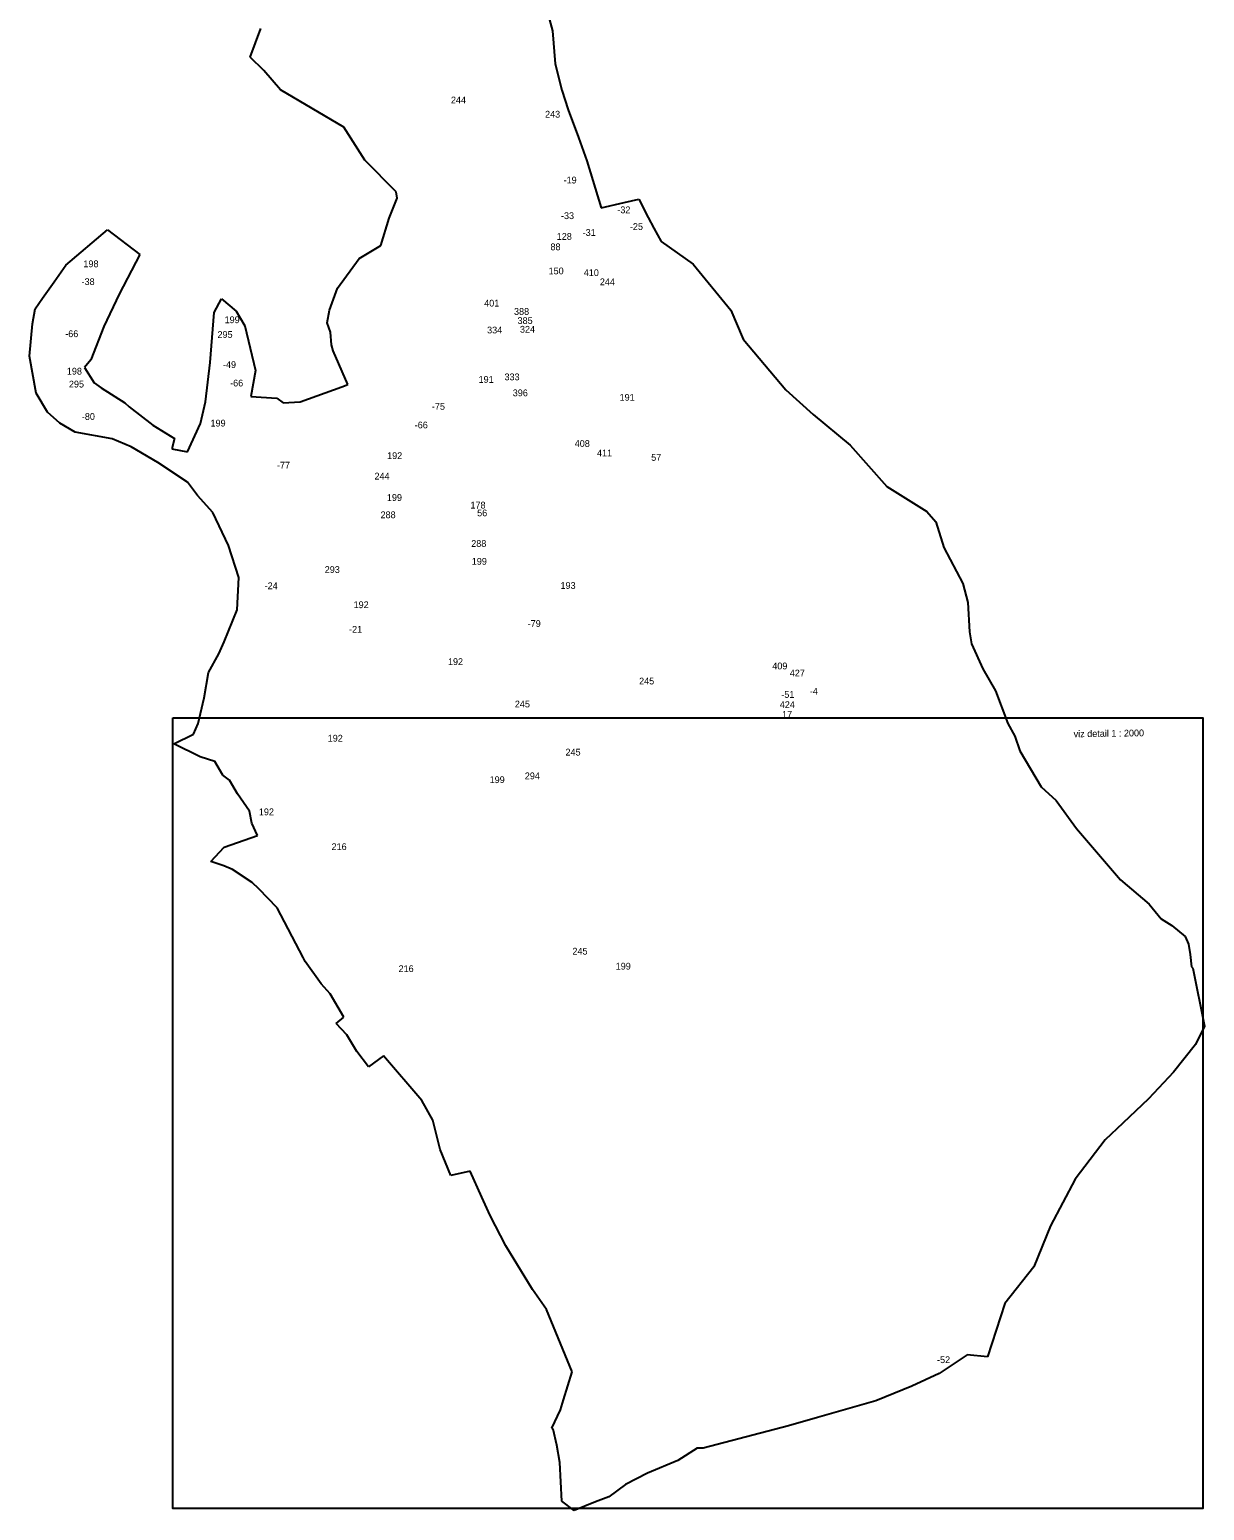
# Model space of a CAD drawing. Extents: x -783664 to -781808, y -970520 to -966149.
# Drawn here: x -783545 to -781808, y -970520 to -968331 of the extents above; entities that cross this region are included whole.
import ezdxf

# ---------------------------------------------------------------- set-up
doc = ezdxf.new("R2010")
doc.units = 0
for name, color, linetype in [('Vrstva 1', 7, 'Continuous'), ('Vrstva 13', 7, 'Continuous'), ('Vrstva 15', 7, 'Continuous'), ('Vrstva 24', 7, 'Continuous')]:
    doc.layers.add(name, color=color, linetype=linetype)

msp = doc.modelspace()

# ---------------------------------------------------------------- linework, layer by layer
at = {"layer": 'Vrstva 1'}
msp.add_lwpolyline([(-783332.78, -969348.53), (-781809.77, -969348.53), (-781809.77, -970517.05), (-783332.78, -970517.05)], close=True, dxfattribs=at)
at = {"layer": 'Vrstva 13'}
for p, q in [((-782785.02, -968283.61), (-782771.42, -968332.9)), ((-783218.65, -968371.67), (-783202.86, -968329.23)), ((-782771.42, -968332.9), (-782767.35, -968381.74)), ((-783198.33, -968391.67), (-783218.65, -968371.67)), ((-782767.35, -968381.74), (-782757.92, -968420.6)), ((-783173.85, -968419.84), (-783198.33, -968391.67)), ((-783079.89, -968475.16), (-783173.85, -968419.84)), ((-782757.92, -968420.6), (-782748.39, -968449.45)), ((-782748.39, -968449.45), (-782732.98, -968490.32)), ((-783048.86, -968523.96), (-783079.89, -968475.16)), ((-782732.98, -968490.32), (-782720.6, -968524.88)), ((-783002.81, -968571), (-783048.86, -968523.96)), ((-782720.6, -968524.88), (-782699.6, -968594.28)), ((-783013.22, -968609.55), (-783001.16, -968580.41)), ((-783001.16, -968580.41), (-783002.81, -968571)), ((-782665.4, -968586.72), (-782644.04, -968581.46)), ((-782644.04, -968581.46), (-782630.19, -968608.89)), ((-782699.6, -968594.28), (-782665.4, -968586.72)), ((-783491.11, -968679.04), (-783429.44, -968627.1)), ((-783429.44, -968627.1), (-783381.69, -968663.25)), ((-783025.52, -968650.37), (-783013.22, -968609.55)), ((-782630.19, -968608.89), (-782621.5, -968624.39)), ((-782621.5, -968624.39), (-782610.6, -968644.1)), ((-783057.4, -968669.3), (-783025.52, -968650.37)), ((-782610.6, -968644.1), (-782563.43, -968677.86)), ((-783381.69, -968663.25), (-783412.28, -968722.15)), ((-783089.45, -968713.02), (-783057.4, -968669.3)), ((-783508.5, -968703.81), (-783491.11, -968679.04)), ((-782563.43, -968677.86), (-782507.85, -968745.93)), ((-783525.33, -968728.26), (-783508.5, -968703.81)), ((-783101.43, -968745.57), (-783089.45, -968713.02)), ((-783536.41, -968743.8), (-783525.33, -968728.26)), ((-783412.28, -968722.15), (-783434.93, -968769.71)), ((-783271.61, -968749.07), (-783261, -968729.07)), ((-783261, -968729.07), (-783239.26, -968747.45)), ((-783540.46, -968765.98), (-783536.41, -968743.8)), ((-783277.76, -968823.19), (-783271.61, -968749.07)), ((-783239.26, -968747.45), (-783226.3, -968768.75)), ((-783104.67, -968764.55), (-783101.43, -968745.57)), ((-782507.85, -968745.93), (-782489.71, -968788.49)), ((-783544.62, -968813.93), (-783540.46, -968765.98)), ((-783434.93, -968769.71), (-783453.95, -968819.26)), ((-783226.3, -968768.75), (-783210.59, -968834.9)), ((-783099.6, -968778.26), (-783104.67, -968764.55)), ((-783098.43, -968797), (-783099.6, -968778.26)), ((-783095.84, -968805.66), (-783098.43, -968797)), ((-782489.71, -968788.49), (-782426.6, -968863.6)), ((-783534.79, -968868.55), (-783544.62, -968813.93)), ((-783453.95, -968819.26), (-783463.41, -968830.51)), ((-783284.32, -968881.4), (-783277.76, -968823.19)), ((-783074.23, -968855.61), (-783095.84, -968805.66)), ((-783463.41, -968830.51), (-783449.1, -968852.95)), ((-783210.59, -968834.9), (-783217.48, -968873.35)), ((-783518.29, -968896.55), (-783534.79, -968868.55)), ((-783449.1, -968852.95), (-783438.74, -968860.64)), ((-783438.74, -968860.64), (-783403.94, -968882.58)), ((-783144.57, -968881.23), (-783082.73, -968859.01)), ((-783082.73, -968859.01), (-783074.23, -968855.61)), ((-782426.6, -968863.6), (-782385.87, -968900.18)), ((-783403.94, -968882.58), (-783397.31, -968888.48)), ((-783397.31, -968888.48), (-783362.51, -968915.76)), ((-783291.89, -968913.28), (-783284.32, -968881.4)), ((-783217.48, -968873.35), (-783178.87, -968875.62)), ((-783178.87, -968875.62), (-783169.49, -968882.97)), ((-783169.49, -968882.97), (-783144.57, -968881.23)), ((-783499.76, -968912.58), (-783518.29, -968896.55)), ((-783477.1, -968925.91), (-783499.76, -968912.58)), ((-783310.96, -968955.27), (-783291.89, -968913.28)), ((-782385.87, -968900.18), (-782331.5, -968945.35)), ((-783422.32, -968935.86), (-783477.1, -968925.91)), ((-783362.51, -968915.76), (-783330.54, -968935.35)), ((-783330.54, -968935.35), (-783334.1, -968950.97)), ((-783394.32, -968947.79), (-783422.32, -968935.86)), ((-783355.25, -968971.09), (-783394.32, -968947.79)), ((-783334.1, -968950.97), (-783310.96, -968955.27)), ((-782331.5, -968945.35), (-782277.13, -969006.38)), ((-783310.98, -968999.84), (-783355.25, -968971.09)), ((-783296.25, -969019.92), (-783310.98, -968999.84)), ((-783273.6, -969044.93), (-783296.25, -969019.92)), ((-782277.13, -969006.38), (-782218.19, -969043.45)), ((-783250.3, -969093.64), (-783273.6, -969044.93)), ((-782218.19, -969043.45), (-782204.92, -969058.74)), ((-782204.92, -969058.74), (-782192.78, -969096.46)), ((-783235.11, -969140.72), (-783250.3, -969093.64)), ((-782192.78, -969096.46), (-782164.94, -969149.63)), ((-783237.54, -969188.69), (-783235.11, -969140.72)), ((-782164.94, -969149.63), (-782157.18, -969177.8)), ((-783256.84, -969235.91), (-783237.54, -969188.69)), ((-782157.18, -969177.8), (-782154.95, -969221.17)), ((-783264.61, -969253.64), (-783256.84, -969235.91)), ((-782154.95, -969221.17), (-782151.79, -969238.98)), ((-782151.79, -969238.98), (-782135.05, -969275.73)), ((-783279.9, -969281.15), (-783264.61, -969253.64)), ((-783286.61, -969318.95), (-783279.9, -969281.15)), ((-782135.05, -969275.73), (-782116.6, -969308.58)), ((-783295.27, -969356.79), (-783286.61, -969318.95)), ((-782116.6, -969308.58), (-782098.25, -969356.65)), ((-783331.36, -969386.74), (-783302.23, -969372.49)), ((-783302.23, -969372.49), (-783295.27, -969356.79)), ((-782098.25, -969356.65), (-782087.84, -969375.47)), ((-783292.52, -969406.16), (-783331.36, -969386.74)), ((-782087.84, -969375.47), (-782080.69, -969397.33)), ((-783270.68, -969412.96), (-783292.52, -969406.16)), ((-783258.93, -969433.08), (-783270.68, -969412.96)), ((-782080.69, -969397.33), (-782048.95, -969450.39)), ((-783249.14, -969440.28), (-783258.93, -969433.08)), ((-783237.33, -969460.76), (-783249.14, -969440.28)), ((-783219.6, -969486.34), (-783237.33, -969460.76)), ((-782048.95, -969450.39), (-782026.97, -969470.38)), ((-782026.97, -969470.38), (-781996.67, -969511.79)), ((-783216.12, -969503.99), (-783219.6, -969486.34)), ((-783207.54, -969522.48), (-783216.12, -969503.99)), ((-783256.74, -969539.31), (-783207.54, -969522.48)), ((-781996.67, -969511.79), (-781931.64, -969587.59)), ((-783276.8, -969560.88), (-783256.74, -969539.31)), ((-783257.3, -969566.96), (-783276.8, -969560.88)), ((-783244.76, -969572.78), (-783257.3, -969566.96)), ((-783215.47, -969591.64), (-783244.76, -969572.78)), ((-783205.92, -969600.87), (-783215.47, -969591.64)), ((-781931.64, -969587.59), (-781889.25, -969623.85)), ((-783178.66, -969629.28), (-783205.92, -969600.87)), ((-783140.31, -969702.61), (-783178.66, -969629.28)), ((-781889.25, -969623.85), (-781871.53, -969645.22)), ((-781871.53, -969645.22), (-781855.91, -969655.18)), ((-781855.91, -969655.18), (-781836.17, -969671.53)), ((-781836.17, -969671.53), (-781831.32, -969682.78)), ((-781831.32, -969682.78), (-781828.47, -969698.32)), ((-781828.47, -969698.32), (-781826.81, -969716.53)), ((-783136.99, -969708.6), (-783140.31, -969702.61)), ((-783113.37, -969741.38), (-783136.99, -969708.6)), ((-781826.81, -969716.53), (-781824.54, -969718.27)), ((-781824.54, -969718.27), (-781807.61, -969803.88)), ((-783100.1, -969756.36), (-783113.37, -969741.38)), ((-783079.88, -969790.93), (-783100.1, -969756.36)), ((-783091.45, -969800.31), (-783079.88, -969790.93)), ((-783075.67, -969817.07), (-783091.45, -969800.31)), ((-781807.61, -969803.88), (-781820.66, -969831.23)), ((-783068.31, -969829.29), (-783075.67, -969817.07)), ((-783060.7, -969841.51), (-783068.31, -969829.29)), ((-781820.66, -969831.23), (-781853.24, -969871.95)), ((-783043.63, -969864.42), (-783060.7, -969841.51)), ((-783021.3, -969847.82), (-783043.63, -969864.42)), ((-782964.83, -969914.11), (-783021.3, -969847.82)), ((-781853.24, -969871.95), (-781890.14, -969911.77)), ((-782948.65, -969943.13), (-782964.83, -969914.11)), ((-781890.14, -969911.77), (-781928.24, -969947.55)), ((-782937.56, -969986.47), (-782948.65, -969943.13)), ((-781928.24, -969947.55), (-781954.54, -969972.24)), ((-781954.54, -969972.24), (-781998.8, -970030.27)), ((-782921.87, -970024.8), (-782937.56, -969986.47)), ((-782892.99, -970018.21), (-782921.87, -970024.8)), ((-782876.07, -970056.7), (-782892.99, -970018.21)), ((-781998.8, -970030.27), (-782035.04, -970099.23)), ((-782863.45, -970083.89), (-782876.07, -970056.7)), ((-782840.64, -970128.89), (-782863.45, -970083.89)), ((-782035.04, -970099.23), (-782059.84, -970159.85)), ((-782801.24, -970193.6), (-782840.64, -970128.89)), ((-782059.84, -970159.85), (-782102.86, -970214)), ((-782780.12, -970223.14), (-782801.24, -970193.6)), ((-782742.43, -970315.26), (-782780.12, -970223.14)), ((-782102.86, -970214), (-782128.22, -970293.13)), ((-782158.28, -970290.05), (-782199.7, -970317.41)), ((-782128.22, -970293.13), (-782158.28, -970290.05)), ((-782755.22, -970356.46), (-782742.43, -970315.26)), ((-782240.08, -970336.27), (-782293.56, -970357.89)), ((-782199.7, -970317.41), (-782240.08, -970336.27)), ((-782759.9, -970371.1), (-782755.22, -970356.46)), ((-782293.56, -970357.89), (-782379.82, -970382.57)), ((-782772.28, -970398.46), (-782759.9, -970371.1)), ((-782770.51, -970399.67), (-782772.28, -970398.46)), ((-782764.93, -970423.59), (-782770.51, -970399.67)), ((-782422.63, -970394.89), (-782548.61, -970428.07)), ((-782379.82, -970382.57), (-782422.63, -970394.89)), ((-782760.72, -970449), (-782764.93, -970423.59)), ((-782557.66, -970428.12), (-782586.14, -970446.17)), ((-782548.61, -970428.07), (-782557.66, -970428.12)), ((-782757.57, -970506.02), (-782760.72, -970449)), ((-782631.04, -970464.71), (-782663.48, -970481.62)), ((-782586.14, -970446.17), (-782631.04, -970464.71)), ((-782663.48, -970481.62), (-782688.4, -970499.71)), ((-782739.21, -970519.86), (-782757.57, -970506.02)), ((-782708.14, -970507.16), (-782739.21, -970519.86)), ((-782688.4, -970499.71), (-782708.14, -970507.16))]:
    msp.add_line(p, q, dxfattribs=at)

# ---------------------------------------------------------------- texts
at = {"layer": 'Vrstva 15'}
for s, p in [('244', (-782921.678, -968440.11)), ('243', (-782782.472, -968461.12)), ('-19', (-782755.078, -968558.49)), ('-33', (-782758.97, -968611.14)), ('-32', (-782675.63, -968602.51)), ('-31', (-782726.874, -968635.96)), ('-25', (-782657.04, -968627.17)), ('88', (-782774.486, -968657.16)), ('128', (-782765.241, -968641.8)), ('410', (-782725.237, -968695.3)), ('-38', (-783467.84, -968708.6)), ('244', (-782701.488, -968708.88)), ('-66', (-783491.947, -968785.65)), ('-49', (-783258.72, -968831.22)), ('-66', (-783248.147, -968858.49)), ('-75', (-782949.828, -968892.97)), ('-80', (-783467.39, -968907.95)), ('-66', (-782975.207, -968920.56)), ('411', (-782705.721, -968961.97)), ('-77', (-783178.908, -968979.87)), ('57', (-782625.546, -968968.39)), ('244', (-783034.688, -968996.12)), ('178', (-782892.8, -969038.93)), ('56', (-782882.9, -969050.47)), ('-24', (-783197.116, -969158.18)), ('-21', (-783072.284, -969222.49)), ('-79', (-782808.202, -969213.89)), ('409', (-782446.506, -969276.7)), ('427', (-782420.651, -969287.11)), ('245', (-782643.452, -969298.99)), ('-4', (-782391.026, -969314.06)), ('245', (-782827.152, -969332.94)), ('424', (-782435.438, -969333.86)), ('-51', (-782433.194, -969318.79)), ('17', (-782432.05, -969348.28)), ('245', (-782752.272, -969404.08)), ('245', (-782742.032, -969698.33)), ('-52', (-782202.89, -970302.16))]:
    msp.add_text(s, height=10, dxfattribs=at).set_placement(p)
msp.add_text('viz detail 1 : 2000', height=10, rotation=0.873756, dxfattribs=at).set_placement((-782000.838, -969377.136))
at = {"layer": 'Vrstva 24'}
for s, p in [('198', (-783465.054, -968682.26)), ('150', (-782777.291, -968692.77)), ('401', (-782872.496, -968740.38)), ('199', (-783256.328, -968764.99)), ('388', (-782828.376, -968752.72)), ('385', (-782823.146, -968766.2)), ('295', (-783266.81, -968786.8)), ('334', (-782868.182, -968780.11)), ('324', (-782819.642, -968779.01)), ('198', (-783489.564, -968840.98)), ('191', (-782880.798, -968853.18)), ('333', (-782842.436, -968849.39)), ('295', (-783486.49, -968860.05)), ('396', (-782830.244, -968872.97)), ('191', (-782672.318, -968879.58)), ('199', (-783277.088, -968917.76)), ('192', (-783016.014, -968965.8)), ('408', (-782738.662, -968947.88)), ('199', (-783016.348, -969027.7)), ('288', (-783025.736, -969053.29)), ('288', (-782891.646, -969095.68)), ('293', (-783108.25, -969134.16)), ('199', (-782890.828, -969122.01)), ('193', (-782759.634, -969157.74)), ('192', (-783065.574, -969186.22)), ('192', (-782926.044, -969270.29)), ('192', (-783103.824, -969383.46)), ('199', (-782864.438, -969444.82)), ('294', (-782812.436, -969439.12)), ('192', (-783205.634, -969492.33)), ('216', (-783098.164, -969543.84)), ('216', (-782999.094, -969724.17)), ('199', (-782678.048, -969720.46))]:
    msp.add_text(s, height=10, dxfattribs=at).set_placement(p)

doc.saveas('drawing.dxf')
